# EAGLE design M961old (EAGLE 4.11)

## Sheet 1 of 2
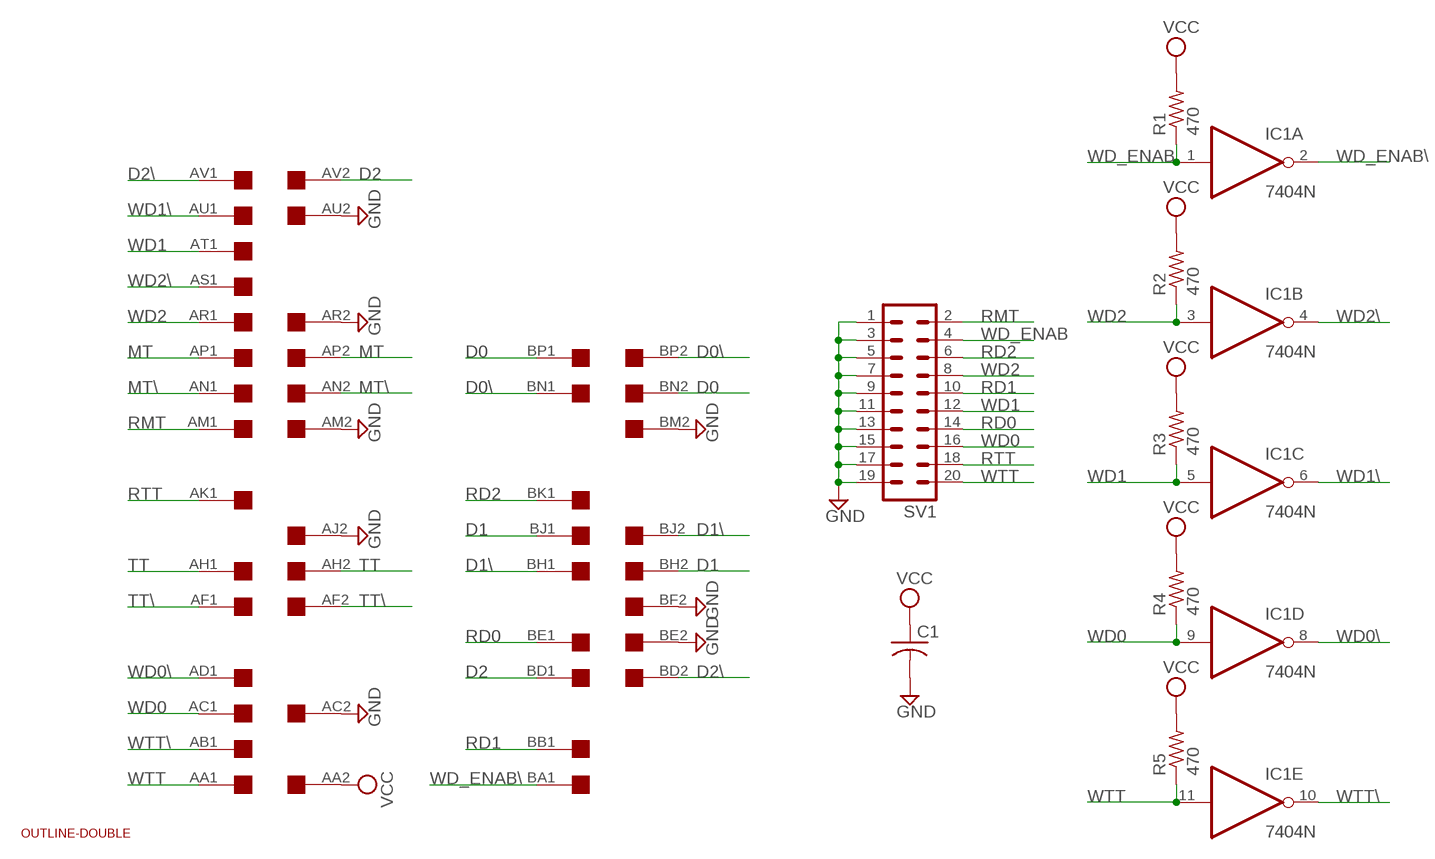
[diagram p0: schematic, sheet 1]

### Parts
C1  C-US050-025X075  [C050-025X075]
EDGE$1  DOUBLE  [EDGE-CON4]
IC1  7404N  [DIL14]
R1  470  R-US_0207/10  [0207/10]
R2  470  R-US_0207/10  [0207/10]
R3  470  R-US_0207/10  [0207/10]
R4  470  R-US_0207/10  [0207/10]
R5  470  R-US_0207/10  [0207/10]
SV1  MA10-2  [MA10-2]
U$2  OUTLINE-DOUBLE  [DOUBLE]

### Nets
D0: EDGE$1.BN2 EDGE$1.BP1
D0\: EDGE$1.BN1 EDGE$1.BP2
D1: EDGE$1.BH2 EDGE$1.BJ1
D1\: EDGE$1.BH1 EDGE$1.BJ2
D2: EDGE$1.AV2 EDGE$1.BD1
D2\: EDGE$1.AV1 EDGE$1.BD2
GND: C1.2 EDGE$1.AC2 EDGE$1.AJ2 EDGE$1.AM2 EDGE$1.AR2 EDGE$1.AU2 EDGE$1.BE2 EDGE$1.BF2 EDGE$1.BM2 SV1.1 SV1.3 SV1.5 SV1.7 SV1.9 SV1.11 SV1.13 SV1.15 SV1.17 SV1.19 ; also sheet 2
MT: EDGE$1.AP1 EDGE$1.AP2
MT\: EDGE$1.AN1 EDGE$1.AN2
RD0: EDGE$1.BE1 SV1.14 ; also sheet 2
RD1: EDGE$1.BB1 SV1.10 ; also sheet 2
RD2: EDGE$1.BK1 SV1.6 ; also sheet 2
RMT: EDGE$1.AM1 SV1.2 ; also sheet 2
RTT: EDGE$1.AK1 SV1.18 ; also sheet 2
TT: EDGE$1.AH1 EDGE$1.AH2
TT\: EDGE$1.AF1 EDGE$1.AF2
VCC: C1.1 EDGE$1.AA2 R1.2 R2.2 R3.2 R4.2 R5.2
WD0: EDGE$1.AC1 IC1.9(D:I) R4.1 SV1.16 ; also sheet 2
WD0\: EDGE$1.AD1 IC1.8(D:O)
WD1: EDGE$1.AT1 IC1.5(C:I) R3.1 SV1.12 ; also sheet 2
WD1\: EDGE$1.AU1 IC1.6(C:O)
WD2: EDGE$1.AR1 IC1.3(B:I) R2.1 SV1.8 ; also sheet 2
WD2\: EDGE$1.AS1 IC1.4(B:O)
WD_ENAB: IC1.1(A:I) R1.1 SV1.4 ; also sheet 2
WD_ENAB\: EDGE$1.BA1 IC1.2(A:O)
WTT: EDGE$1.AA1 IC1.11(E:I) R5.1 SV1.20 ; also sheet 2
WTT\: EDGE$1.AB1 IC1.10(E:O)
Unconnected: EDGE$1.AB2 EDGE$1.AD2 EDGE$1.AE1 EDGE$1.AE2 EDGE$1.AJ1 EDGE$1.AK2 EDGE$1.AL1 EDGE$1.AL2 EDGE$1.AS2 EDGE$1.AT2 EDGE$1.BA2 EDGE$1.BB2 EDGE$1.BC1 EDGE$1.BC2 EDGE$1.BF1 EDGE$1.BK2 EDGE$1.BL1 EDGE$1.BL2 EDGE$1.BM1 EDGE$1.BR1 EDGE$1.BR2 EDGE$1.BS1 EDGE$1.BS2 EDGE$1.BT1 EDGE$1.BT2 EDGE$1.BU1 EDGE$1.BU2 EDGE$1.BV1 EDGE$1.BV2 IC1.12(F:O) IC1.13(F:I)

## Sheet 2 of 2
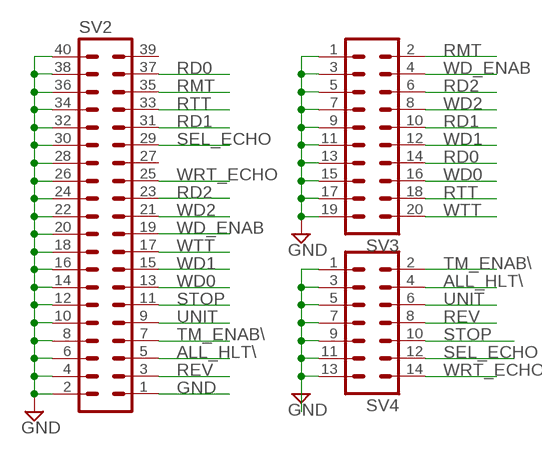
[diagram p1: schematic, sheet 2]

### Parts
SV2  MA20-2  [MA20-2]
SV3  MA10-2  [MA10-2]
SV4  MA07-2  [MA07-2]

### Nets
ALL_HLT\: SV2.5 SV4.4
GND: SV2.1 SV2.2 SV2.4 SV2.6 SV2.8 SV2.10 SV2.12 SV2.14 SV2.16 SV2.18 SV2.20 SV2.22 SV2.24 SV2.26 SV2.28 SV2.30 SV2.32 SV2.34 SV2.36 SV2.38 SV2.40 SV3.1 SV3.3 SV3.5 SV3.7 SV3.9 SV3.11 SV3.13 SV3.15 SV3.17 SV3.19 SV4.1 SV4.3 SV4.5 SV4.7 SV4.9 SV4.11 SV4.13 ; also sheet 1
RD0: SV2.37 SV3.14 ; also sheet 1
RD1: SV2.31 SV3.10 ; also sheet 1
RD2: SV2.23 SV3.6 ; also sheet 1
REV: SV2.3 SV4.8
RMT: SV2.35 SV3.2 ; also sheet 1
RTT: SV2.33 SV3.18 ; also sheet 1
SEL_ECHO: SV2.29 SV4.12
STOP: SV2.11 SV4.10
TM_ENAB\: SV2.7 SV4.2
UNIT: SV2.9 SV4.6
WD0: SV2.13 SV3.16 ; also sheet 1
WD1: SV2.15 SV3.12 ; also sheet 1
WD2: SV2.21 SV3.8 ; also sheet 1
WD_ENAB: SV2.19 SV3.4 ; also sheet 1
WRT_ECHO: SV2.25 SV4.14
WTT: SV2.17 SV3.20 ; also sheet 1
Unconnected: SV2.27 SV2.39

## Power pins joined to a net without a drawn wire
GND: IC1.7(P:GND)
VCC: IC1.14(P:VCC)

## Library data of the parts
C1 = rcl:C-US: CAPACITOR, American symbol
EDGE$1 = dec-con:DOUBLE: Double-Height DEC board
IC1 = 74xx-us:74*04: Hex INVERTER
R1-R5 = rcl:R-US_: RESISTOR, American symbol
SV1 SV3 = con-lstb:MA10-2: PIN HEADER
SV2 = con-lstb:MA20-2: PIN HEADER
SV4 = con-lstb:MA07-2: PIN HEADER
U$2 = dec-con:OUTLINE-*: Board outlines for DEC boards.

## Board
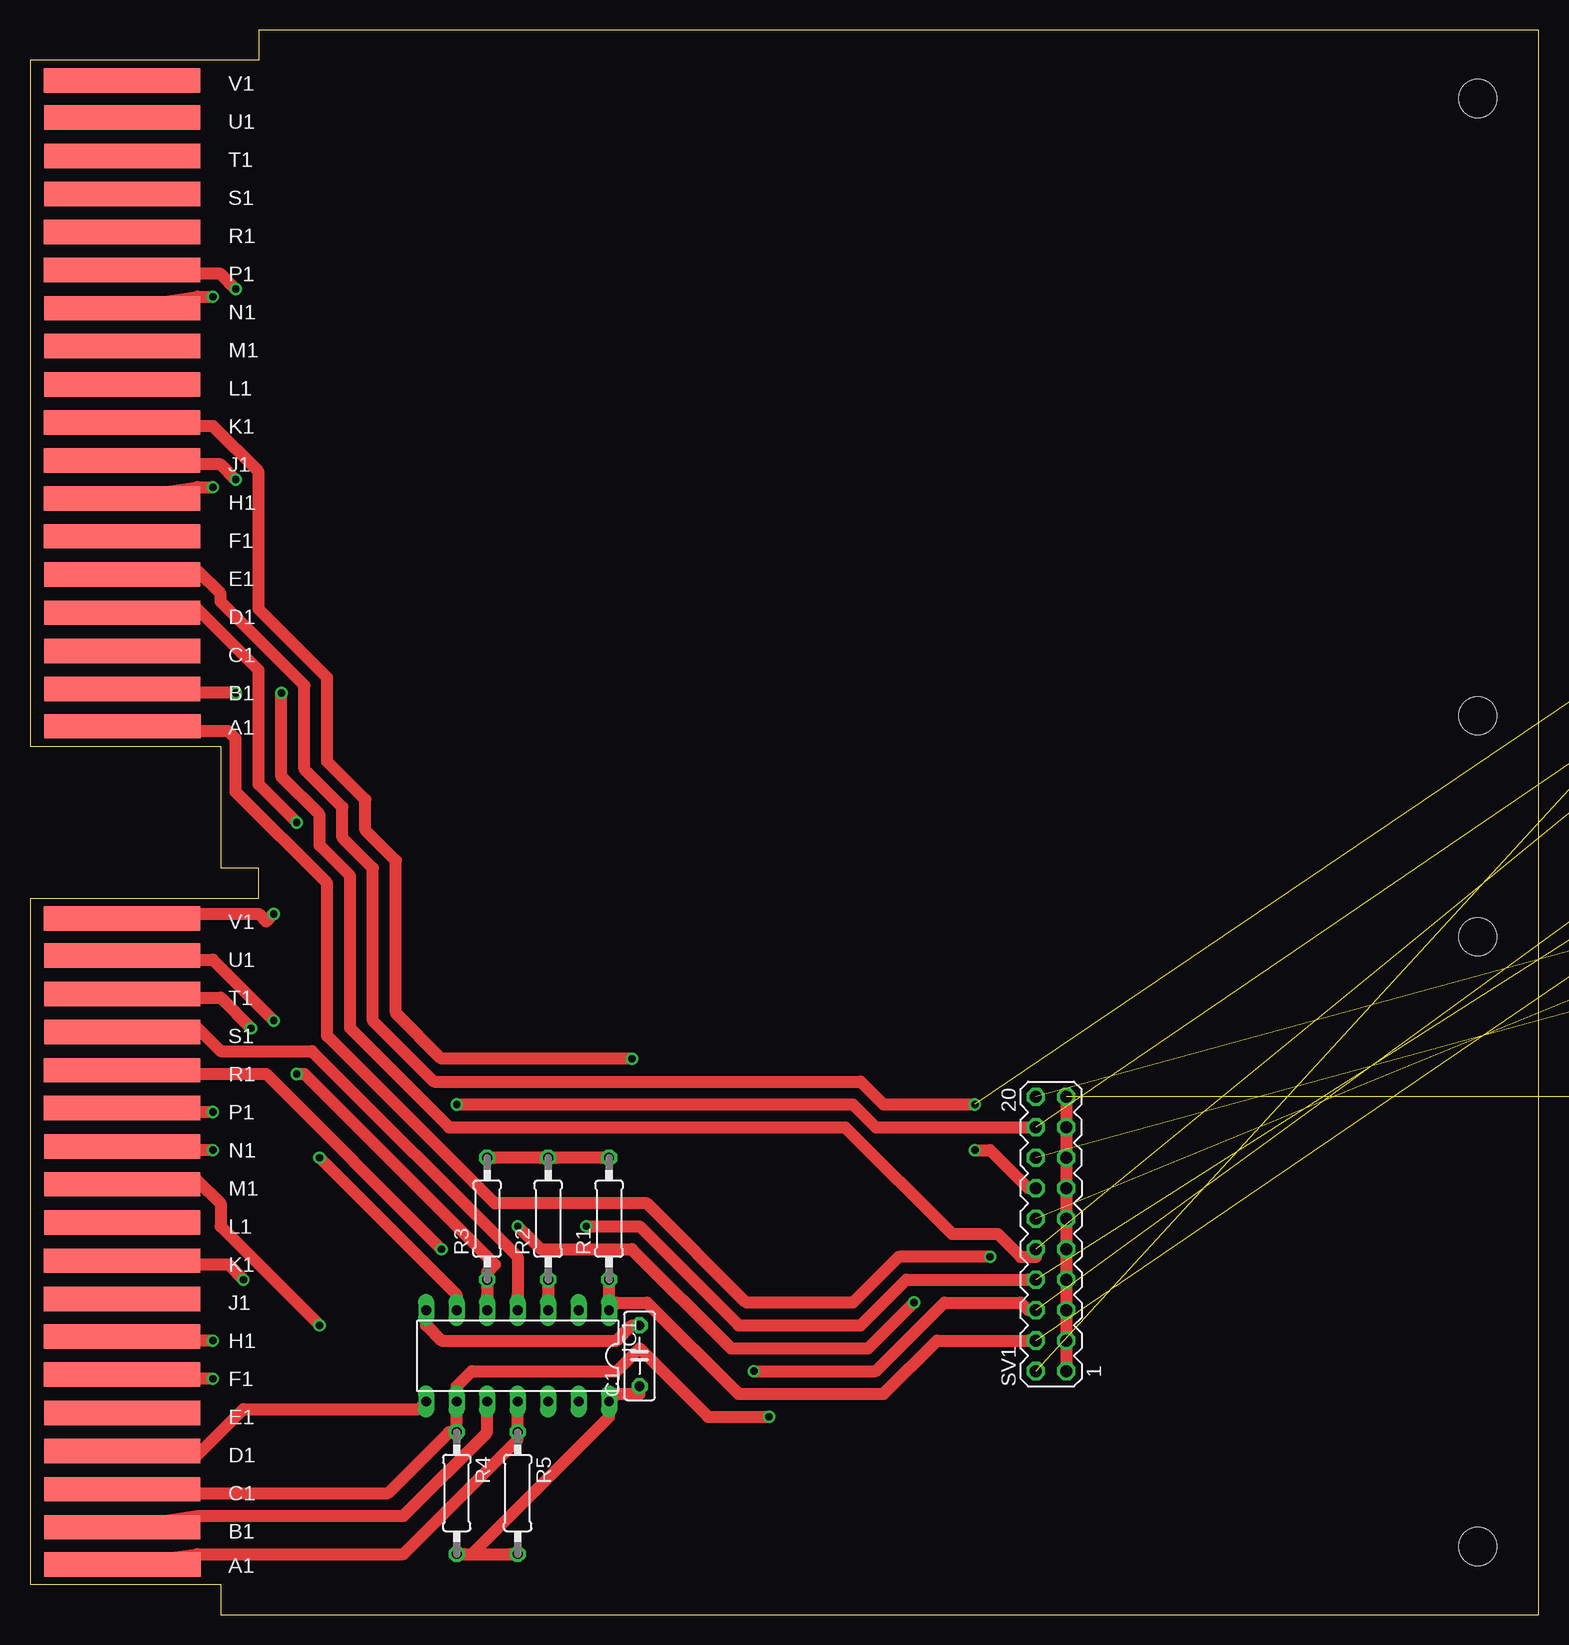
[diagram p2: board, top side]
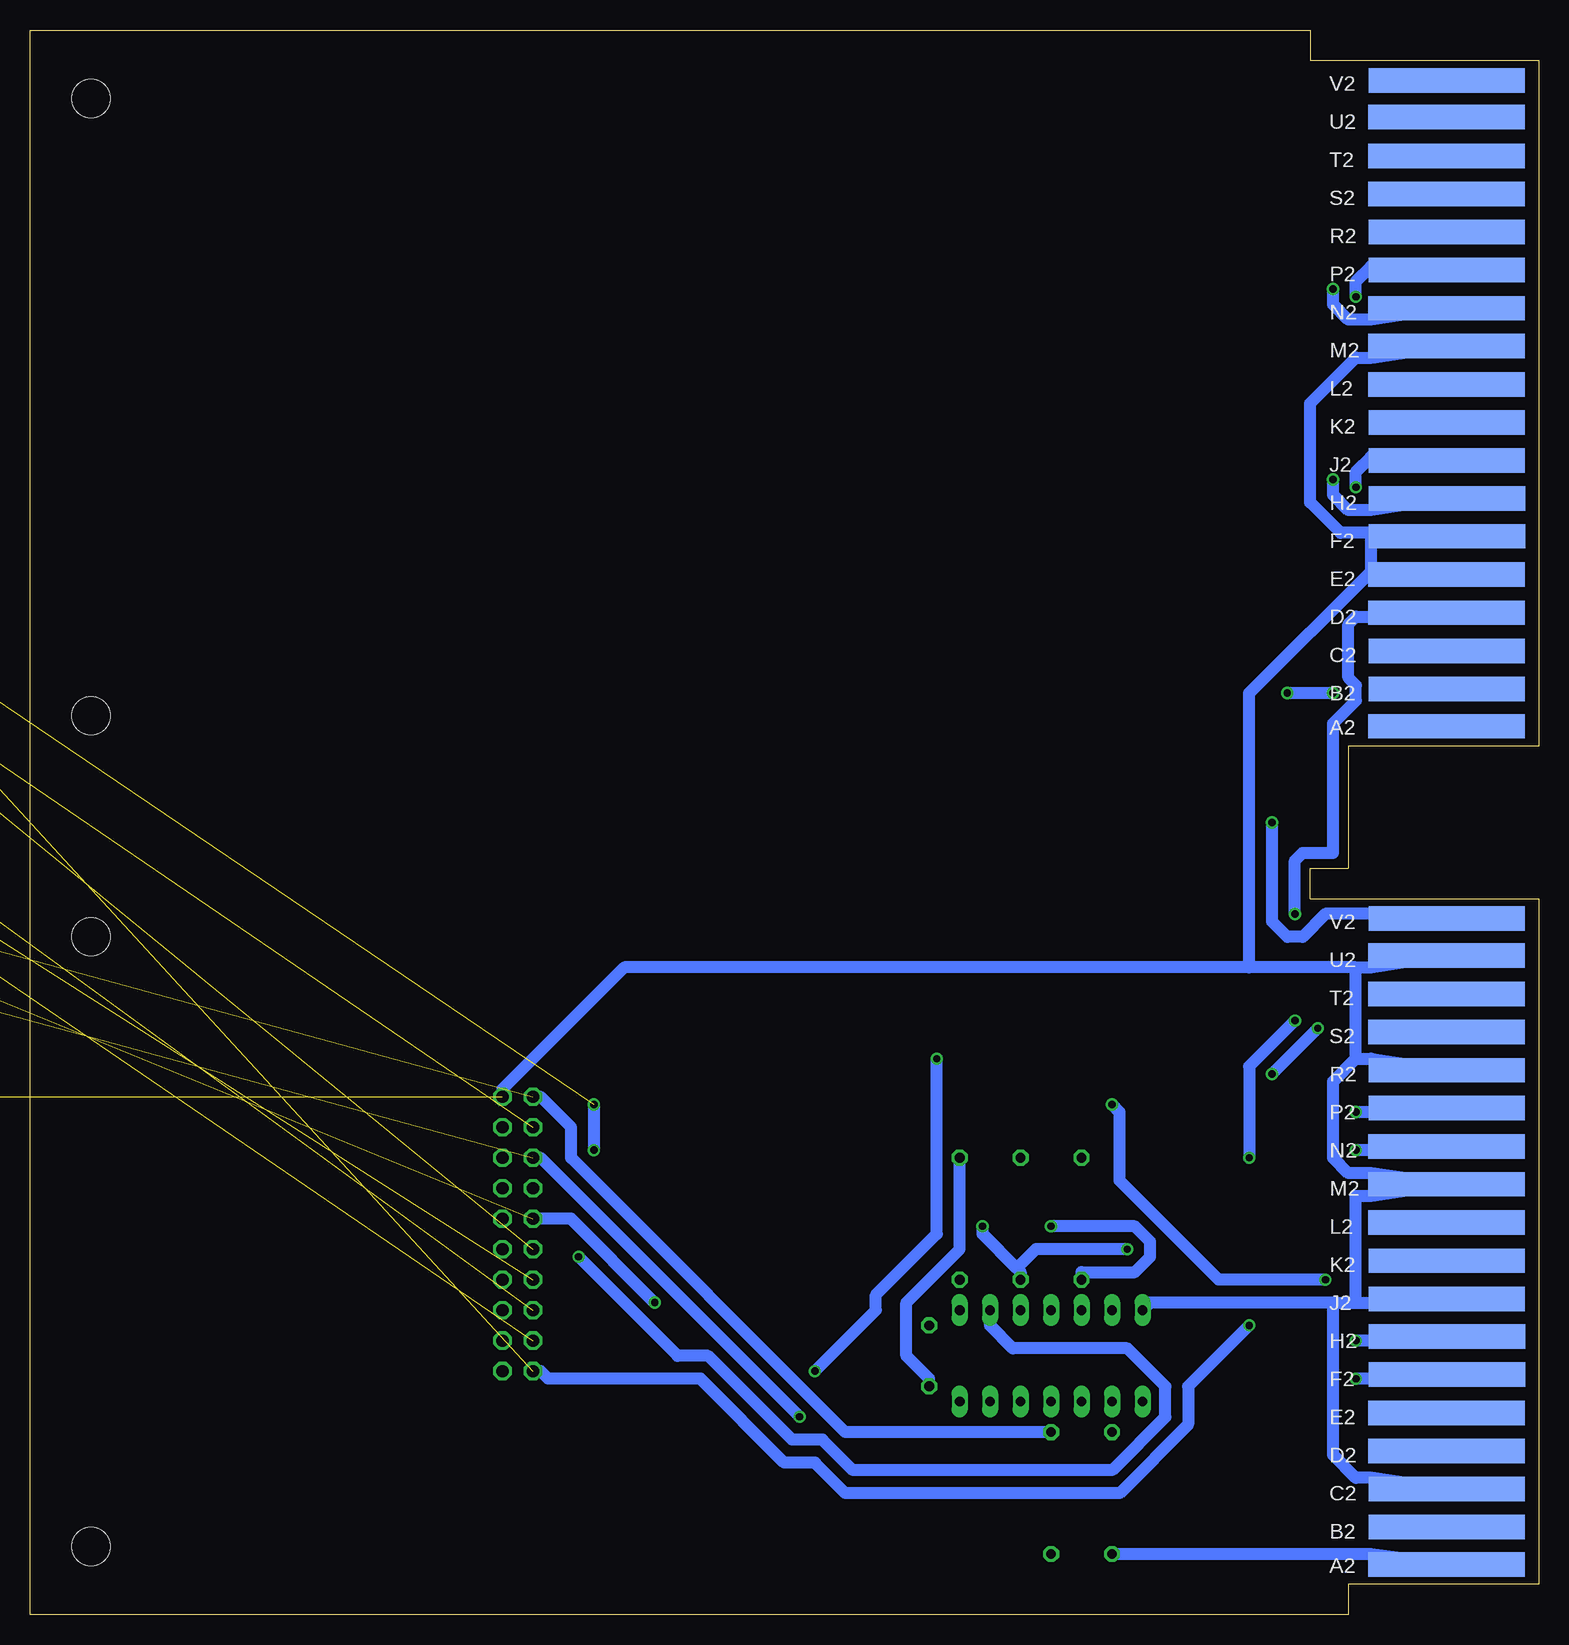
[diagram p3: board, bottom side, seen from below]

Size 125.73 x 132.08 mm. Coordinates in mm from the lower left corner, seen from the top.
Copper layers (1*16): Top 0.035mm / dielectric 1.5mm / Bottom 0.035mm
Design rules "40mils": minimum track width 40mil, minimum drill 24mil, track to track 20mil, track to pad 10mil, pad to pad 10mil, via to via 10mil, smd to smd 10mil, copper to edge 25mil, drill to drill 10mil, minimum pad ring 10mil, minimum via ring 8mil, stop-mask expansion 0mil, vias tented up to drill 0mil, thermal gap 10mil

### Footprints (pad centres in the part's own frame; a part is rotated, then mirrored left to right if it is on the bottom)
C050-025X075 = drill 0.813 octagon: 1 -2.54,0; 2 2.54,0
EDGE-CON4 = smd 13.017 x 2.032: AA1 7.709,4.207; AB1 7.684,7.312; AC1 7.684,10.474; AD1 7.684,13.665; AE1 7.693,16.84; AF1 7.668,20.041; AH1 7.668,23.19; AJ1 7.668,26.34; AK1 7.668,29.515; AL1 7.693,32.69; AM1 7.693,35.89; AN1 7.693,39.04; AP1 7.668,42.24; AR1 7.668,45.39; AS1 7.693,48.565; AT1 7.693,51.74; AU1 7.693,54.94; AV1 7.668,58.026; BA1 7.709,74.057; BB1 7.684,77.162; BC1 7.684,80.324; BD1 7.684,83.515; BE1 7.693,86.69; BF1 7.668,89.891; BH1 7.668,93.04; BJ1 7.668,96.19; BK1 7.668,99.365; BL1 7.693,102.54; BM1 7.693,105.74; BN1 7.693,108.89; BP1 7.668,112.09; BR1 7.668,115.24; BS1 7.693,118.415; BT1 7.693,121.59; BU1 7.693,124.79; BV1 7.668,127.876 | smd 13.017 x 2.032 bottom: AA2 7.69,4.207; AB2 7.668,7.328; AC2 7.668,10.49; AD2 7.693,13.665; AE2 7.693,16.84; AF2 7.642,20.041; AH2 7.642,23.19; AJ2 7.668,26.34; AK2 7.668,29.515; AL2 7.693,32.69; AM2 7.693,35.89; AN2 7.693,39.04; AP2 7.668,42.24; AR2 7.668,45.39; AS2 7.693,48.565; AT2 7.693,51.74; AU2 7.693,54.966; AV2 7.668,58.026; BA2 7.69,74.057; BB2 7.668,77.178; BC2 7.668,80.34; BD2 7.693,83.515; BE2 7.693,86.69; BF2 7.642,89.891; BH2 7.642,93.04; BJ2 7.668,96.19; BK2 7.668,99.365; BL2 7.693,102.54; BM2 7.693,105.74; BN2 7.693,108.89; BP2 7.668,112.09; BR2 7.668,115.24; BS2 7.693,118.415; BT2 7.693,121.59; BU2 7.693,124.816; BV2 7.668,127.876
DIL14 = drill 0.813 long: 1 -7.62,-3.81; 2 -5.08,-3.81; 3 -2.54,-3.81; 4 0,-3.81; 5 2.54,-3.81; 6 5.08,-3.81; 7 7.62,-3.81; 8 7.62,3.81; 9 5.08,3.81; 10 2.54,3.81; 11 0,3.81; 12 -2.54,3.81; 13 -5.08,3.81; 14 -7.62,3.81
0207/10 = drill 0.813 octagon: 1 -5.08,0; 2 5.08,0
MA10-2 = drill 1.016 octagon: 1 -11.43,-1.27; 2 -11.43,1.27; 3 -8.89,-1.27; 4 -8.89,1.27; 5 -6.35,-1.27; 6 -6.35,1.27; 7 -3.81,-1.27; 8 -3.81,1.27; 9 -1.27,-1.27; 10 -1.27,1.27; 11 1.27,-1.27; 12 1.27,1.27; 13 3.81,-1.27; 14 3.81,1.27; 15 6.35,-1.27; 16 6.35,1.27; 17 8.89,-1.27; 18 8.89,1.27; 19 11.43,-1.27; 20 11.43,1.27
MA20-2 = drill 1.016 octagon: 1 -24.13,-1.27; 2 -24.13,1.27; 3 -21.59,-1.27; 4 -21.59,1.27; 5 -19.05,-1.27; 6 -19.05,1.27; 7 -16.51,-1.27; 8 -16.51,1.27; 9 -13.97,-1.27; 10 -13.97,1.27; 11 -11.43,-1.27; 12 -11.43,1.27; 13 -8.89,-1.27; 14 -8.89,1.27; 15 -6.35,-1.27; 16 -6.35,1.27; 17 -3.81,-1.27; 18 -3.81,1.27; 19 -1.27,-1.27; 20 -1.27,1.27; 21 1.27,-1.27; 22 1.27,1.27; 23 3.81,-1.27; 24 3.81,1.27; 25 6.35,-1.27; 26 6.35,1.27; 27 8.89,-1.27; 28 8.89,1.27; 29 11.43,-1.27; 30 11.43,1.27; 31 13.97,-1.27; 32 13.97,1.27; 33 16.51,-1.27; 34 16.51,1.27; 35 19.05,-1.27; 36 19.05,1.27; 37 21.59,-1.27; 38 21.59,1.27; 39 24.13,-1.27; 40 24.13,1.27
MA07-2 = drill 1.016 octagon: 1 -7.62,-1.27; 2 -7.62,1.27; 3 -5.08,-1.27; 4 -5.08,1.27; 5 -2.54,-1.27; 6 -2.54,1.27; 7 0,-1.27; 8 0,1.27; 9 2.54,-1.27; 10 2.54,1.27; 11 5.08,-1.27; 12 5.08,1.27; 13 7.62,-1.27; 14 7.62,1.27
DOUBLE = hole 3.175: 120.65,56.515; 120.65,5.715; 120.65,74.93; 120.65,126.365

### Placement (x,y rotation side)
C1  50.8,21.59 90 top
EDGE$1  0,0 0 top
IC1  40.64,21.59 180 top
R1  48.26,33.02 90 top
R2  43.18,33.02 90 top
R3  38.1,33.02 90 top
R4  35.56,10.16 270 top
R5  40.64,10.16 270 top
SV1  85.09,31.75 90 top
SV2  not placed on the board
SV3  not placed on the board
SV4  not placed on the board
U$2  0,0 0 top

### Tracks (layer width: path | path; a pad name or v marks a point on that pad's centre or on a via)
ALL_HLT\  (1 unrouted)
D0  (via drill 0.61)
  Top 1.016: v17.15,110.49 15.88,111.76 13.97,111.76 EDGE$1.BP1
  Bottom 1.016: v17.15,110.49 17.15,109.22 15.88,107.95 13.97,107.95 EDGE$1.BN2
D0\  (via drill 0.61)
  Top 1.016: v15.24,109.86 13.97,109.86 EDGE$1.BN1
  Bottom 1.016: v15.24,109.86 15.24,111.12 13.97,112.39 EDGE$1.BP2
D1  (via drill 0.61)
  Top 1.016: v17.15,94.61 15.88,95.89 13.97,95.89 EDGE$1.BJ1
  Bottom 1.016: v17.15,94.61 17.15,93.34 15.88,92.08 13.97,92.08 EDGE$1.BH2
D1\  (via drill 0.61)
  Top 1.016: v15.24,93.98 13.97,93.98 EDGE$1.BH1
  Bottom 1.016: v15.24,93.98 15.24,95.25 13.97,96.52 EDGE$1.BJ2
D2  (via drill 0.61)
  Top 1.016: v22.23,66.04 19.05,69.22 19.05,78.74 13.97,83.82 EDGE$1.BD1
  Bottom 1.016: v22.23,66.04 22.23,57.78 20.96,56.52 19.69,56.52 17.78,58.42 13.97,58.42 EDGE$1.AV2
D2\  (via drill 0.61)
  Top 1.016: v20.32,58.42 19.69,57.78 19.05,58.42 13.97,58.42 EDGE$1.AV1
  Bottom 1.016: v20.32,58.42 20.32,62.87 19.69,63.5 17.15,63.5 17.15,74.3 15.24,76.2 15.24,77.47 15.88,78.11 15.88,82.55 15.24,83.19 13.97,83.19 EDGE$1.BD2
GND  (38 unrouted)
  Top 1.016: C1.2 50.17,24.13 48.9,22.86 34.29,22.86 33.02,24.13 IC1.7 | SV1.1 SV1.3 SV1.5 SV1.7 SV1.9 SV1.11 SV1.13 SV1.15 SV1.17 SV1.19
  Bottom 1.016: 15.24,26.04 13.97,26.04 EDGE$1.AJ2 | 17.15,26.04 15.24,26.04 | 17.15,26.04 32.39,26.04 IC1.7 | 17.15,26.04 17.15,13.34 15.24,11.43 13.97,11.43 EDGE$1.AC2 | 15.24,26.04 15.24,34.92 13.97,34.92 EDGE$1.AM2 13.97,36.83 15.88,36.83 17.15,38.1 17.15,44.45 15.24,46.35 | 13.97,87 13.97,86.36 EDGE$1.BE2 13.97,87 | 13.97,87 13.97,90.17 | EDGE$1.BM2 13.97,104.78 15.24,104.78 19.05,100.97 19.05,92.71 16.51,90.17 13.97,90.17 | 15.24,53.98 13.97,53.98 EDGE$1.AU2 | 15.24,53.98 24.13,53.98 | 24.13,53.98 76.2,53.98 86.36,43.81 SV1.19 | 15.24,46.35 13.97,46.35 EDGE$1.AR2 | 15.24,46.35 15.24,53.98 | 13.97,90.17 EDGE$1.BF2 | 13.97,87 24.13,76.83 24.13,53.98
MT  (via drill 0.61)
  Top 1.016: v15.24,41.91 13.97,41.91 EDGE$1.AP2
  Bottom 1.016: v15.24,41.91 13.97,41.91 EDGE$1.AP2
MT\  (via drill 0.61)
  Top 1.016: v15.24,38.73 13.97,38.73 EDGE$1.AN2
  Bottom 1.016: v15.24,38.73 13.97,38.73 EDGE$1.AN2
RD0  (via drill 0.61)  (2 unrouted)
  Top 1.016: v78.74,38.73 80.01,38.73 83.19,35.56 SV1.14 | v78.74,42.55 71.12,42.55 69.22,44.45 33.66,44.45 28.58,49.53 28.58,62.23 26.04,64.77 26.04,67.31 22.86,70.48 22.86,77.47 15.88,84.45 15.88,85.09 13.97,87 EDGE$1.BE1
  Bottom 1.016: v78.74,42.55 v78.74,38.73
RD1  (via drill 0.61)  (2 unrouted)
  Top 1.016: v17.15,76.83 13.97,76.83 EDGE$1.BB1 | v20.96,76.83 20.96,69.85 24.13,66.67 24.13,64.14 26.67,61.59 26.67,48.9 34.93,40.64 67.95,40.64 76.84,31.75 80.65,31.75 82.55,29.84 83.82,29.84 SV1.10
  Bottom 1.016: v20.96,76.83 v17.15,76.83
RD2  (via drill 0.61)  (2 unrouted)
  Top 1.016: v60.33,20.32 70.49,20.32 76.2,26.04 82.55,26.04 83.19,25.4 SV1.6 | v50.17,46.35 34.29,46.35 30.48,50.16 30.48,62.87 27.94,65.41 27.94,67.94 24.77,71.12 24.77,78.11 19.05,83.82 19.05,95.25 15.24,99.06 13.97,99.06 EDGE$1.BK1
  Bottom 1.016: v60.33,20.32 55.25,25.4 55.25,26.67 50.17,31.75 v50.17,46.35
REV  (1 unrouted)
RMT  (via drill 0.61)  (2 unrouted)
  Top 1.016: v24.13,24.13 15.88,32.38 15.88,34.29 13.97,36.2 EDGE$1.AM1
  Bottom 1.016: v24.13,24.13 29.21,19.05 29.21,15.88 34.93,10.16 57.79,10.16 60.33,12.7 62.87,12.7 69.85,19.68 82.55,19.68 83.19,20.32 SV1.2
RTT  (via drill 0.61)  (2 unrouted)
  Top 1.016: v17.78,27.94 16.51,29.21 13.97,29.21 EDGE$1.AK1 | v35.56,42.55 68.58,42.55 70.49,40.64 83.19,40.64 SV1.18
  Bottom 1.016: v17.78,27.94 26.67,27.94 34.93,36.2 34.93,41.91 v35.56,42.55
SEL_ECHO  (1 unrouted)
STOP  (1 unrouted)
TM_ENAB\  (1 unrouted)
TT  (via drill 0.61)
  Top 1.016: v15.24,22.86 13.97,22.86 EDGE$1.AH1
  Bottom 1.016: v15.24,22.86 13.97,22.86 EDGE$1.AH2
TT\  (via drill 0.61)
  Top 1.016: v15.24,19.68 13.97,19.68 EDGE$1.AF1
  Bottom 1.016: v15.24,19.68 13.97,19.68 EDGE$1.AF2
UNIT  (1 unrouted)
VCC
  Top 1.016: R3.2 38.74,38.1 42.55,38.1 R2.2 43.82,38.1 47.63,38.1 R1.2 | C1.1 50.8,18.41 48.9,18.41 IC1.14 48.26,16.51 36.83,5.08 | 36.83,5.08 40.01,5.08 R5.2 | 36.83,5.08 36.2,5.08 R4.2
  Bottom 1.016: R1.2 48.26,37.47 48.26,30.48 52.71,26.04 52.71,21.59 50.8,19.68 C1.1 | EDGE$1.AA2 13.97,5.08 34.93,5.08 R4.2
WD0  (via drill 0.61)  (2 unrouted)
  Top 1.016: v61.6,16.51 56.52,16.51 50.8,22.23 48.9,20.32 36.83,20.32 35.56,19.05 IC1.9 35.56,16.51 35.56,15.88 R4.1 34.93,15.24 29.85,10.16 13.97,10.16 EDGE$1.AC1
  Bottom 1.016: v61.6,16.51 83.19,38.1 SV1.16
WD0\
  Top 1.016: IC1.8 32.39,17.14 17.78,17.14 13.97,13.34 EDGE$1.AD1
WD1  (via drill 0.61)  (2 unrouted)
  Top 1.016: v18.42,48.9 15.88,51.44 13.97,51.44 EDGE$1.AT1 | v22.23,45.09 22.86,45.09 38.74,29.21 38.1,28.57 R3.1 38.1,27.3 38.1,26.67 IC1.5 | v73.66,26.04 69.85,22.23 58.42,22.23 50.17,30.48 42.55,30.48 v40.64,32.38
  Bottom 1.016: v18.42,48.9 v22.23,45.09 | v73.66,26.04 80.65,33.02 83.19,33.02 SV1.12 | v40.64,32.38 33.66,32.38 32.39,31.11 32.39,29.84 33.66,28.57 38.1,28.57 R3.1
WD1\  (via drill 0.61)
  Top 1.016: v24.13,38.1 35.56,26.67 IC1.6 | v20.32,49.53 15.24,54.61 13.97,54.61 EDGE$1.AU1
  Bottom 1.016: v24.13,38.1 24.13,45.72 v20.32,49.53
WD2  (via drill 0.61)  (2 unrouted)
  Top 1.016: IC1.3 43.18,26.67 43.18,27.3 R2.1 | v46.36,32.38 50.8,32.38 59.06,24.13 69.22,24.13 73.03,27.94 83.19,27.94 SV1.8 | v34.29,30.48 19.69,45.09 13.97,45.09 EDGE$1.AR1
  Bottom 1.016: v46.36,32.38 46.36,31.75 43.5,28.89 | 43.5,28.89 43.18,28.57 R2.1 | v34.29,30.48 41.91,30.48 43.18,29.21 43.5,28.89
WD2\
  Top 1.016: IC1.4 40.64,26.67 40.64,29.84 23.5,46.99 15.88,46.99 13.97,48.9 EDGE$1.AS1
WD_ENAB  (2 unrouted)
  Top 1.016: R1.1 48.26,27.3 48.26,26.67 IC1.1 48.9,26.04 51.44,26.04 59.06,18.41 71.12,18.41 75.57,22.86 83.19,22.86 SV1.4
WD_ENAB\  (via drill 0.61)
  Top 1.016: v80.01,29.84 72.39,29.84 68.58,26.04 59.69,26.04 51.44,34.29 38.74,34.29 24.77,48.26 24.77,60.96 17.15,68.58 17.15,73.03 16.51,73.66 13.97,73.66 EDGE$1.BA1
  Bottom 1.016: v80.01,29.84 71.76,21.59 69.22,21.59 62.23,14.61 59.69,14.61 57.15,12.06 35.56,12.06 31.12,16.51 31.12,19.05 34.29,22.23 43.82,22.23 45.72,24.13 IC1.2
WRT_ECHO  (1 unrouted)
WTT  (2 unrouted)
  Top 1.016: IC1.11 40.64,16.51 40.64,15.88 R5.1 40.64,14.61 31.12,5.08 13.97,5.08 EDGE$1.AA1
  Bottom 1.016: SV1.20 83.19,43.18 80.65,40.64 80.65,38.1 57.79,15.24 41.28,15.24 R5.1
WTT\
  Top 1.016: IC1.10 38.1,16.51 38.1,15.24 31.12,8.26 13.97,8.26 EDGE$1.AB1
